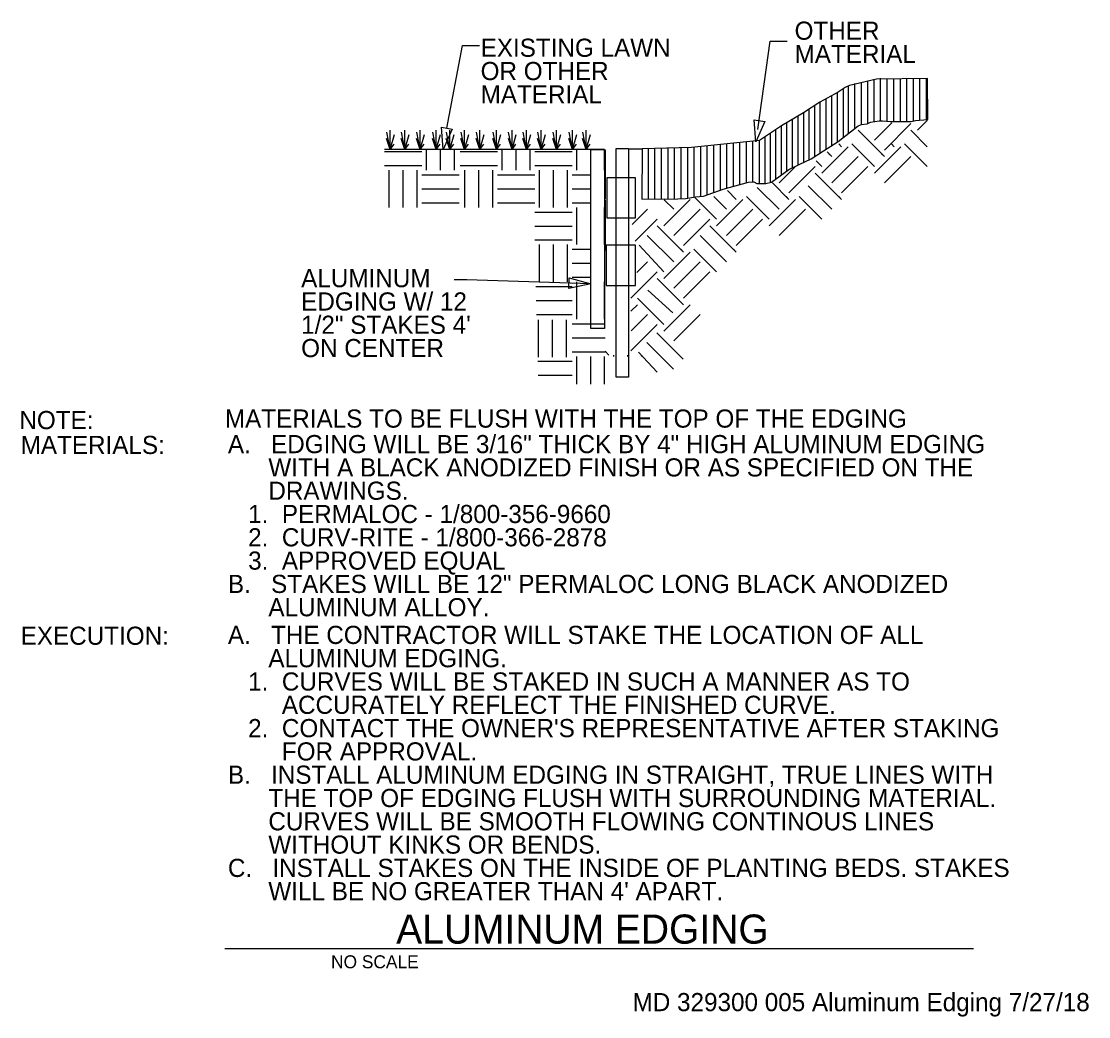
# Model space of a CAD drawing. Extents: x 10145.4 to 10186.6, y 9970.3 to 10008.7.
import ezdxf

# ---------------------------------------------------------------- set-up
doc = ezdxf.new("R2010")
doc.units = 0
for name, color, linetype in [('Default', 7, 'Continuous'), ('G-ANNO-CELL', 7, 'Continuous'), ('G-ANNO-TEXT', 7, 'Continuous'), ('G-DETL-GRID', 7, 'Continuous'), ('G-DETL-LINE', 7, 'Continuous'), ('G-DETL-OTLN', 7, 'Continuous'), ('G-DETL-PATT', 7, 'Continuous'), ('G-DETL-TEXT', 7, 'Continuous')]:
    doc.layers.add(name, color=color, linetype=linetype)

# ---------------------------------------------------------------- blocks, each defined once
blk = doc.blocks.new('TERARR')
at = {"layer": 'Default'}
blk.add_lwpolyline([(-0.667, 0.167), (0, 0), (-0.667, -0.167)], close=True, dxfattribs=at)

msp = doc.modelspace()

# ---------------------------------------------------------------- linework, layer by layer
at = {"layer": 'G-ANNO-TEXT'}
msp.add_line((10153.294, 9972.936), (10182.188, 9972.936), dxfattribs=at)
msp.add_line((10153.294, 9972.936), (10182.188, 9972.936), dxfattribs=at)
at = {"layer": 'G-DETL-LINE'}
for p, q in [((10159.674, 10003.773), (10159.532, 10004.193)), ((10159.674, 10003.773), (10159.544, 10004.437)), ((10159.674, 10003.773), (10159.674, 10004.513)), ((10159.674, 10003.773), (10159.84, 10004.346)), ((10160.236, 10003.773), (10160.094, 10004.193)), ((10160.236, 10003.773), (10160.106, 10004.437)), ((10160.236, 10003.773), (10160.236, 10004.513)), ((10160.236, 10003.773), (10160.402, 10004.346)), ((10160.827, 10003.773), (10160.685, 10004.193)), ((10160.827, 10003.773), (10160.697, 10004.437)), ((10160.827, 10003.773), (10160.827, 10004.513)), ((10160.827, 10003.773), (10160.993, 10004.346)), ((10161.447, 10003.773), (10161.305, 10004.193)), ((10161.447, 10003.773), (10161.317, 10004.437)), ((10161.447, 10003.773), (10161.447, 10004.513)), ((10161.447, 10003.773), (10161.613, 10004.346)), ((10161.979, 10003.773), (10161.838, 10004.193)), ((10161.979, 10003.773), (10161.838, 10004.193)), ((10161.979, 10003.773), (10161.85, 10004.437)), ((10161.979, 10003.773), (10161.85, 10004.437)), ((10161.979, 10003.773), (10161.979, 10004.513)), ((10161.979, 10003.773), (10161.979, 10004.513)), ((10161.979, 10003.773), (10162.145, 10004.346)), ((10161.979, 10003.773), (10162.145, 10004.346)), ((10162.541, 10003.773), (10162.399, 10004.193)), ((10162.541, 10003.773), (10162.412, 10004.437)), ((10162.541, 10003.773), (10162.541, 10004.513)), ((10162.541, 10003.773), (10162.707, 10004.346)), ((10163.132, 10003.773), (10162.99, 10004.193)), ((10163.132, 10003.773), (10163.003, 10004.437)), ((10163.132, 10003.773), (10163.132, 10004.513)), ((10163.132, 10003.773), (10163.298, 10004.346)), ((10163.782, 10003.773), (10163.64, 10004.193)), ((10163.782, 10003.773), (10163.652, 10004.437)), ((10163.782, 10003.773), (10163.782, 10004.513)), ((10163.782, 10003.773), (10163.948, 10004.346)), ((10164.375, 10003.773), (10164.234, 10004.193)), ((10164.375, 10003.773), (10164.246, 10004.437)), ((10164.375, 10003.773), (10164.375, 10004.513)), ((10164.375, 10003.773), (10164.541, 10004.346)), ((10164.937, 10003.773), (10164.795, 10004.193)), ((10164.937, 10003.773), (10164.808, 10004.437)), ((10164.937, 10003.773), (10164.937, 10004.513)), ((10164.937, 10003.773), (10165.103, 10004.346)), ((10165.499, 10003.773), (10165.357, 10004.193)), ((10165.499, 10003.773), (10165.369, 10004.437)), ((10165.499, 10003.773), (10165.499, 10004.513)), ((10165.499, 10003.773), (10165.665, 10004.346)), ((10166.09, 10003.773), (10165.948, 10004.193)), ((10166.09, 10003.773), (10165.96, 10004.437)), ((10166.09, 10003.773), (10166.09, 10004.513)), ((10166.09, 10003.773), (10166.256, 10004.346)), ((10166.71, 10003.773), (10166.569, 10004.193)), ((10166.71, 10003.773), (10166.581, 10004.437)), ((10166.71, 10003.773), (10166.71, 10004.513)), ((10166.71, 10003.773), (10166.876, 10004.346)), ((10167.243, 10003.773), (10167.101, 10004.193)), ((10167.243, 10003.773), (10167.113, 10004.437)), ((10167.243, 10003.773), (10167.243, 10004.513)), ((10167.243, 10003.773), (10167.409, 10004.346)), ((10159.674, 10003.773), (10159.828, 10003.975)), ((10160.236, 10003.773), (10160.389, 10003.975)), ((10160.827, 10003.773), (10160.98, 10003.975)), ((10161.447, 10003.773), (10161.601, 10003.975)), ((10161.979, 10003.773), (10162.133, 10003.975)), ((10161.979, 10003.773), (10162.133, 10003.975)), ((10162.541, 10003.773), (10162.695, 10003.975)), ((10163.132, 10003.773), (10163.286, 10003.975)), ((10163.782, 10003.773), (10163.936, 10003.975)), ((10164.375, 10003.773), (10164.529, 10003.975)), ((10164.937, 10003.773), (10165.091, 10003.975)), ((10165.499, 10003.773), (10165.653, 10003.975)), ((10166.09, 10003.773), (10166.244, 10003.975)), ((10166.71, 10003.773), (10166.864, 10003.975)), ((10167.243, 10003.773), (10167.397, 10003.975))]:
    msp.add_line(p, q, dxfattribs=at)
at = {"layer": 'G-DETL-OTLN'}
for p, q in [((10177.402, 10006.238), (10177.236, 10006.163)), ((10178.442, 10006.493), (10177.402, 10006.238)), ((10180.407, 10006.515), (10178.442, 10006.493)), ((10180.425, 10004.926), (10180.407, 10006.515)), ((10176.958, 10005.98), (10176.254, 10005.605)), ((10177.236, 10006.163), (10176.958, 10005.98)), ((10176.254, 10005.605), (10175.627, 10005.191)), ((10175.627, 10005.191), (10174.781, 10004.686)), ((10174.781, 10004.686), (10173.928, 10004.116)), ((10176.963, 10004.084), (10177.729, 10004.688)), ((10177.729, 10004.688), (10177.861, 10004.738)), ((10177.861, 10004.738), (10178.087, 10004.768)), ((10178.087, 10004.768), (10178.214, 10004.827)), ((10178.214, 10004.827), (10178.548, 10004.878)), ((10178.548, 10004.878), (10178.677, 10004.881)), ((10178.677, 10004.881), (10178.969, 10004.854)), ((10178.969, 10004.854), (10179.777, 10004.857)), ((10179.777, 10004.857), (10179.952, 10004.887)), ((10179.952, 10004.887), (10180.425, 10004.926)), ((10167.95, 10003.773), (10159.448, 10003.773)), ((10169.399, 10003.804), (10169.386, 10001.853)), ((10171.297, 10003.853), (10169.399, 10003.804)), ((10173.429, 10004.066), (10171.297, 10003.853)), ((10173.928, 10004.116), (10173.429, 10004.066)), ((10175.925, 10003.416), (10176.394, 10003.718)), ((10176.394, 10003.718), (10176.963, 10004.084)), ((10175.459, 10003.19), (10175.925, 10003.416)), ((10174.39, 10002.508), (10175.063, 10002.998)), ((10175.063, 10002.998), (10175.459, 10003.19)), ((10172.52, 10002.24), (10173.505, 10002.511)), ((10173.505, 10002.511), (10173.706, 10002.521)), ((10173.706, 10002.521), (10173.823, 10002.464)), ((10174.176, 10002.464), (10174.39, 10002.508)), ((10171.771, 10001.971), (10172.52, 10002.24)), ((10173.823, 10002.464), (10174.176, 10002.464)), ((10169.386, 10001.853), (10170.769, 10001.867)), ((10170.769, 10001.867), (10171.083, 10001.884)), ((10171.083, 10001.884), (10171.451, 10001.951)), ((10171.451, 10001.951), (10171.771, 10001.971))]:
    msp.add_line(p, q, dxfattribs=at)
for points in [[(10167.411, 10003.773), (10167.95, 10003.773), (10167.95, 9996.86), (10167.411, 9996.86)], [(10168.389, 10003.81), (10168.873, 10003.81), (10168.873, 9994.981), (10168.389, 9994.981)], [(10169.138, 10002.683), (10168.038, 10002.683), (10168.038, 10001.131), (10169.138, 10001.131)], [(10169.138, 10000.085), (10168.014, 10000.085), (10168.014, 9998.528), (10169.138, 9998.528)]]:
    msp.add_lwpolyline(points, close=True, dxfattribs=at)
for points in [[(10167.989, 10001.869), (10167.989, 10003.76)], [(10168.864, 10003.804), (10169.397, 10003.804)], [(10167.989, 9999.881), (10167.989, 10001.824)]]:
    msp.add_lwpolyline(points, dxfattribs=at)
at = {"layer": 'G-DETL-PATT'}
for p, q in [((10177.402, 10006.238), (10177.236, 10006.163)), ((10177.352, 10006.237), (10177.352, 10004.389)), ((10178.442, 10006.493), (10177.402, 10006.238)), ((10177.592, 10006.323), (10177.592, 10004.579)), ((10177.85, 10006.347), (10177.85, 10004.735)), ((10178.095, 10006.407), (10178.095, 10004.771)), ((10178.341, 10006.467), (10178.341, 10004.844)), ((10180.407, 10006.515), (10178.442, 10006.493)), ((10178.587, 10006.527), (10178.587, 10004.877)), ((10178.843, 10006.496), (10178.843, 10004.867)), ((10179.096, 10006.499), (10179.096, 10004.855)), ((10179.349, 10006.502), (10179.349, 10004.856)), ((10179.602, 10006.505), (10179.602, 10004.856)), ((10179.855, 10006.508), (10179.855, 10004.869)), ((10180.107, 10006.511), (10180.107, 10004.9)), ((10180.36, 10006.514), (10180.36, 10004.92)), ((10180.425, 10004.926), (10180.407, 10006.515)), ((10176.958, 10005.98), (10176.254, 10005.605)), ((10176.704, 10005.843), (10176.704, 10003.917)), ((10176.927, 10005.962), (10176.927, 10004.059)), ((10177.236, 10006.163), (10176.958, 10005.98)), ((10177.15, 10006.082), (10177.15, 10004.235)), ((10176.254, 10005.605), (10175.627, 10005.191)), ((10176.047, 10005.466), (10176.047, 10003.494)), ((10176.258, 10005.606), (10176.258, 10003.631)), ((10176.481, 10005.724), (10176.481, 10003.774)), ((10175.627, 10005.191), (10174.781, 10004.686)), ((10175.408, 10005.058), (10175.408, 10003.165)), ((10175.625, 10005.188), (10175.625, 10003.27)), ((10175.836, 10005.327), (10175.836, 10003.374)), ((10174.781, 10004.686), (10173.928, 10004.116)), ((10174.757, 10004.668), (10174.757, 10002.776)), ((10174.967, 10004.809), (10174.967, 10002.928)), ((10175.19, 10004.929), (10175.19, 10003.059)), ((10176.963, 10004.084), (10177.729, 10004.688)), ((10177.729, 10004.688), (10177.861, 10004.738)), ((10177.861, 10004.738), (10178.087, 10004.768)), ((10178.087, 10004.768), (10178.214, 10004.827)), ((10178.214, 10004.827), (10178.548, 10004.878)), ((10178.367, 10004.135), (10179.032, 10004.8)), ((10178.548, 10004.878), (10178.677, 10004.881)), ((10178.677, 10004.881), (10178.969, 10004.854)), ((10178.748, 10003.753), (10179.764, 10004.77)), ((10178.969, 10004.854), (10179.777, 10004.857)), ((10179.777, 10004.857), (10179.952, 10004.887)), ((10179.952, 10004.887), (10180.425, 10004.926)), ((10180.019, 10004.516), (10180.397, 10004.894)), ((10174.126, 10004.247), (10174.126, 10002.464)), ((10174.337, 10004.388), (10174.337, 10002.497)), ((10174.547, 10004.528), (10174.547, 10002.624)), ((10178.748, 10003.499), (10177.732, 10004.516)), ((10180.403, 10003.877), (10179.764, 10004.516)), ((10161.072, 10002.976), (10161.072, 10003.773)), ((10161.611, 10002.976), (10161.611, 10003.773)), ((10162.151, 10002.976), (10162.151, 10003.773)), ((10163.997, 10002.976), (10163.997, 10003.773)), ((10164.536, 10002.976), (10164.536, 10003.773)), ((10165.075, 10002.976), (10165.075, 10003.773)), ((10166.872, 10002.976), (10166.872, 10003.773)), ((10167.411, 10002.976), (10167.411, 10003.773)), ((10167.95, 10002.976), (10167.95, 10003.773)), ((10169.399, 10003.804), (10169.386, 10001.853)), ((10171.297, 10003.853), (10169.399, 10003.804)), ((10169.628, 10003.808), (10169.628, 10001.856)), ((10169.873, 10003.816), (10169.873, 10001.857)), ((10170.134, 10003.821), (10170.134, 10001.869)), ((10170.386, 10003.828), (10170.386, 10001.875)), ((10170.639, 10003.835), (10170.639, 10001.882)), ((10170.892, 10003.841), (10170.892, 10001.889)), ((10171.145, 10003.848), (10171.145, 10001.895)), ((10173.429, 10004.066), (10171.297, 10003.853)), ((10171.397, 10003.854), (10171.397, 10001.941)), ((10171.649, 10003.887), (10171.649, 10001.963)), ((10171.9, 10003.912), (10171.9, 10002.017)), ((10172.152, 10003.937), (10172.152, 10002.11)), ((10172.403, 10003.963), (10172.403, 10002.197)), ((10172.655, 10003.988), (10172.655, 10002.279)), ((10172.907, 10004.013), (10172.907, 10002.345)), ((10173.158, 10004.038), (10173.158, 10002.417)), ((10173.41, 10004.063), (10173.41, 10002.485)), ((10173.928, 10004.116), (10173.429, 10004.066)), ((10173.661, 10004.088), (10173.661, 10002.518)), ((10173.913, 10004.114), (10173.913, 10002.465)), ((10175.925, 10003.416), (10176.394, 10003.718)), ((10176.334, 10002.864), (10177.35, 10003.881)), ((10176.394, 10003.718), (10176.963, 10004.084)), ((10177.096, 10003.881), (10176.987, 10003.989)), ((10178.367, 10003.118), (10177.496, 10003.989)), ((10178.748, 10003.499), (10178.258, 10003.989)), ((10178.367, 10002.864), (10179.383, 10003.881)), ((10179.129, 10003.881), (10179.02, 10003.989)), ((10180.4, 10003.118), (10179.528, 10003.989)), ((10179.56, 10004.049), (10179.56, 10004.049)), ((10180.371, 10003.995), (10180.371, 10003.995)), ((10159.455, 10003.694), (10160.893, 10003.694)), ((10162.38, 10003.694), (10163.817, 10003.694)), ((10165.255, 10003.694), (10166.692, 10003.694)), ((10175.459, 10003.19), (10175.925, 10003.416)), ((10176.334, 10003.118), (10176.116, 10003.336)), ((10176.715, 10003.499), (10176.532, 10003.682)), ((10176.715, 10003.499), (10176.606, 10003.608)), ((10176.715, 10002.483), (10177.732, 10003.499)), ((10178.748, 10003.499), (10178.639, 10003.608)), ((10178.748, 10002.483), (10179.764, 10003.499)), ((10179.179, 10003.667), (10179.179, 10003.667)), ((10179.989, 10003.614), (10179.989, 10003.614)), ((10159.455, 10003.155), (10160.893, 10003.155)), ((10159.635, 10001.538), (10159.635, 10002.976)), ((10160.174, 10001.538), (10160.174, 10002.976)), ((10160.713, 10001.538), (10160.713, 10002.976)), ((10162.38, 10003.155), (10163.817, 10003.155)), ((10162.559, 10001.538), (10162.559, 10002.976)), ((10163.098, 10001.538), (10163.098, 10002.976)), ((10163.637, 10001.538), (10163.637, 10002.976)), ((10165.255, 10003.155), (10166.692, 10003.155)), ((10165.434, 10001.538), (10165.434, 10002.976)), ((10165.973, 10001.538), (10165.973, 10002.976)), ((10166.512, 10001.538), (10166.512, 10002.976)), ((10174.39, 10002.508), (10175.063, 10002.998)), ((10174.682, 10002.483), (10175.284, 10003.085)), ((10175.063, 10002.998), (10175.459, 10003.19)), ((10175.063, 10002.102), (10176.08, 10003.118)), ((10177.096, 10002.102), (10178.113, 10003.118)), ((10160.893, 10002.796), (10162.33, 10002.796)), ((10163.817, 10002.796), (10165.255, 10002.796)), ((10166.692, 10002.796), (10167.419, 10002.796)), ((10172.52, 10002.24), (10173.505, 10002.511)), ((10173.505, 10002.511), (10173.706, 10002.521)), ((10173.706, 10002.521), (10173.823, 10002.464)), ((10174.176, 10002.464), (10174.39, 10002.508)), ((10175.063, 10001.848), (10174.425, 10002.485)), ((10177.096, 10001.848), (10176.08, 10002.864)), ((10160.893, 10002.257), (10162.33, 10002.257)), ((10163.817, 10002.257), (10165.255, 10002.257)), ((10166.692, 10002.257), (10167.419, 10002.257)), ((10171.771, 10001.971), (10172.52, 10002.24)), ((10173.03, 10001.848), (10172.686, 10002.192)), ((10173.823, 10002.464), (10174.176, 10002.464)), ((10174.682, 10001.466), (10173.837, 10002.311)), ((10176.715, 10001.466), (10175.81, 10002.371)), ((10160.893, 10001.718), (10162.33, 10001.718)), ((10163.817, 10001.718), (10165.255, 10001.718)), ((10166.692, 10001.718), (10167.426, 10001.718)), ((10169.386, 10001.853), (10170.769, 10001.867)), ((10170.235, 10000.831), (10171.252, 10001.848)), ((10170.616, 10001.466), (10170.249, 10001.834)), ((10170.769, 10001.867), (10171.083, 10001.884)), ((10171.083, 10001.884), (10171.451, 10001.951)), ((10172.268, 10001.085), (10171.397, 10001.957)), ((10171.451, 10001.951), (10171.771, 10001.971)), ((10172.649, 10001.466), (10172.159, 10001.957)), ((10172.268, 10000.831), (10173.284, 10001.848)), ((10174.301, 10001.085), (10173.43, 10001.957)), ((10174.301, 10000.831), (10175.317, 10001.848)), ((10175.063, 10001.848), (10174.954, 10001.957)), ((10175.063, 10001.848), (10174.954, 10001.957)), ((10175.283, 10002.001), (10175.283, 10002.001)), ((10175.283, 10002.001), (10175.283, 10002.001)), ((10176.334, 10001.085), (10175.463, 10001.957)), ((10177.096, 10001.848), (10176.987, 10001.957)), ((10177.096, 10001.848), (10176.987, 10001.957)), ((10165.255, 10001.358), (10166.692, 10001.358)), ((10166.872, 10000.101), (10166.872, 10001.538)), ((10167.411, 10000.101), (10167.411, 10001.538)), ((10167.95, 10000.101), (10167.95, 10001.538)), ((10168.867, 10001.631), (10168.867, 10001.631)), ((10169.008, 10000.874), (10169.6, 10001.466)), ((10170.616, 10000.45), (10171.633, 10001.466)), ((10172.649, 10000.45), (10173.666, 10001.466)), ((10174.682, 10000.45), (10175.699, 10001.466)), ((10168.82, 10001.112), (10168.82, 10001.112)), ((10169.129, 10000.233), (10169.981, 10001.085)), ((10170.997, 9999.815), (10169.981, 10000.831)), ((10170.997, 10000.069), (10172.014, 10001.085)), ((10173.03, 9999.815), (10172.014, 10000.831)), ((10173.03, 10000.069), (10174.047, 10001.085)), ((10165.255, 10000.819), (10166.692, 10000.819)), ((10170.616, 9999.433), (10169.595, 10000.455)), ((10172.649, 9999.433), (10171.633, 10000.45)), ((10165.255, 10000.28), (10166.692, 10000.28)), ((10165.434, 9998.663), (10165.434, 10000.101)), ((10165.973, 9998.663), (10165.973, 10000.101)), ((10166.512, 9998.663), (10166.512, 10000.101)), ((10169.124, 10000.101), (10169.124, 10000.101)), ((10169.277, 10000.084), (10169.277, 10000.084)), ((10170.235, 9999.052), (10169.277, 10000.084)), ((10166.692, 9999.921), (10167.41, 9999.921)), ((10170.235, 9998.798), (10171.252, 9999.815)), ((10170.997, 9999.815), (10170.888, 9999.924)), ((10172.268, 9999.052), (10171.397, 9999.924)), ((10172.649, 9999.433), (10172.159, 9999.924)), ((10173.03, 9999.815), (10172.921, 9999.924)), ((10166.692, 9999.382), (10167.41, 9999.382)), ((10169.193, 9999.027), (10169.6, 9999.433)), ((10170.616, 9998.417), (10171.633, 9999.433)), ((10166.692, 9998.843), (10167.414, 9998.843)), ((10168.964, 9998.036), (10169.981, 9999.052)), ((10170.997, 9997.782), (10169.981, 9998.798)), ((10170.997, 9998.036), (10172.014, 9999.052)), ((10165.292, 9998.483), (10166.692, 9998.483)), ((10166.872, 9997.226), (10166.872, 9998.663)), ((10167.411, 9997.226), (10167.411, 9998.663)), ((10167.95, 9997.226), (10167.95, 9998.663)), ((10165.306, 9997.944), (10166.692, 9997.944)), ((10170.235, 9997.019), (10169.219, 9998.036)), ((10169.616, 9998.342), (10170.577, 9997.47)), ((10168.964, 9997.528), (10169.219, 9997.782)), ((10170.235, 9996.765), (10171.252, 9997.782)), ((10165.32, 9997.405), (10166.692, 9997.405)), ((10165.394, 9995.764), (10165.394, 9997.202)), ((10165.933, 9995.764), (10165.933, 9997.202)), ((10166.472, 9995.764), (10166.472, 9997.202)), ((10168.975, 9996.776), (10169.6, 9997.401)), ((10170.616, 9996.384), (10171.633, 9997.401)), ((10166.692, 9997.046), (10167.964, 9997.046)), ((10168.964, 9996.003), (10169.981, 9997.019)), ((10166.692, 9996.507), (10167.964, 9996.507)), ((10170.601, 9995.301), (10169.58, 9996.322)), ((10170.982, 9995.682), (10169.966, 9996.699)), ((10166.692, 9995.968), (10167.964, 9995.968)), ((10168.11, 9995.841), (10167.964, 9995.987)), ((10169.98, 9995.178), (10169.262, 9995.951)), ((10165.37, 9995.608), (10166.692, 9995.608)), ((10166.872, 9994.71), (10166.872, 9995.788)), ((10167.411, 9994.71), (10167.411, 9995.788)), ((10167.95, 9994.71), (10167.95, 9995.788)), ((10168.309, 9995.788), (10168.309, 9995.841)), ((10168.848, 9995.788), (10168.848, 9995.841)), ((10169.387, 9995.788), (10169.387, 9995.841)), ((10165.386, 9995.069), (10166.692, 9995.069))]:
    msp.add_line(p, q, dxfattribs=at)
for points in [[(10173.864, 10004.538), (10174.336, 10007.953), (10174.992, 10007.953)], [(10161.857, 10004.596), (10162.466, 10007.78), (10163.122, 10007.78)], [(10167.411, 9998.588), (10162.633, 9998.749), (10162.14, 9998.749)]]:
    msp.add_lwpolyline(points, dxfattribs=at)

# ---------------------------------------------------------------- block references
for p, xscale, yscale, rotation in [((10161.722, 10003.774), 1.2500000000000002, 1.25, -99.35282054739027), ((10173.788, 10004.065), 1.2500000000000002, 1.25, -99.35282054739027), ((10167.411, 9998.588), 1.25, 1.2500000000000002, -1.9239204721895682)]:
    msp.add_blockref('TERARR', p, dxfattribs=dict(at, xscale=xscale, yscale=yscale, rotation=rotation))

# ---------------------------------------------------------------- texts
at = {"layer": 'G-ANNO-CELL'}
for s, height, p in [('NO SCALE', 0.5, (10157.392, 9972.175)), ('MD 329300 005 Aluminum Edging 7/27/18', 0.7, (10169.029, 9970.519))]:
    msp.add_text(s, height=height, dxfattribs=at).set_placement(p)
at = {"layer": 'G-DETL-GRID'}
msp.add_text('ALUMINUM EDGING', height=1.125, dxfattribs=at).set_placement((10159.905, 9973.124))
at = {"layer": 'G-DETL-TEXT'}
for s, p in [('OTHER ', (10175.28, 10008.008)), ('EXISTING LAWN ', (10163.164, 10007.35)), ('MATERIAL', (10175.28, 10007.109)), ('OR OTHER ', (10163.164, 10006.451)), ('MATERIAL', (10163.164, 10005.551)), ('ALUMINUM ', (10156.238, 9998.457)), ('EDGING W/ 12 ', (10156.238, 9997.558)), ('1/2" STAKES 4\' ', (10156.238, 9996.659)), ('ON CENTER', (10156.238, 9995.76)), ('NOTE:', (10145.363, 9992.982)), ('MATERIALS TO BE FLUSH WITH THE TOP OF THE EDGING', (10153.295, 9993.039)), ('MATERIALS:', (10145.413, 9992.022)), ('A.   EDGING WILL BE 3/16" THICK BY 4" HIGH ALUMINUM EDGING ', (10153.412, 9992.053)), ('      WITH A BLACK ANODIZED FINISH OR AS SPECIFIED ON THE ', (10153.412, 9991.154)), ('      DRAWINGS.', (10153.412, 9990.255)), ('   1.  PERMALOC - 1/800-356-9660', (10153.412, 9989.356)), ('   2.  CURV-RITE - 1/800-366-2878', (10153.412, 9988.457)), ('   3.  APPROVED EQUAL', (10153.412, 9987.558)), ('B.   STAKES WILL BE 12" PERMALOC LONG BLACK ANODIZED ', (10153.412, 9986.658)), ('      ALUMINUM ALLOY.', (10153.412, 9985.759)), ('EXECUTION:', (10145.413, 9984.658)), ('A.   THE CONTRACTOR WILL STAKE THE LOCATION OF ALL ', (10153.412, 9984.69)), ('      ALUMINUM EDGING.', (10153.412, 9983.791)), ('   1.  CURVES WILL BE STAKED IN SUCH A MANNER AS TO ', (10153.412, 9982.892)), ('        ACCURATELY REFLECT THE FINISHED CURVE.', (10153.412, 9981.993)), ("   2.  CONTACT THE OWNER'S REPRESENTATIVE AFTER STAKING ", (10153.412, 9981.093)), ('        FOR APPROVAL.', (10153.412, 9980.194)), ('B.   INSTALL ALUMINUM EDGING IN STRAIGHT, TRUE LINES WITH ', (10153.412, 9979.295)), ('      THE TOP OF EDGING FLUSH WITH SURROUNDING MATERIAL. ', (10153.412, 9978.396)), ('      CURVES WILL BE SMOOTH FLOWING CONTINOUS LINES ', (10153.412, 9977.497)), ('      WITHOUT KINKS OR BENDS. ', (10153.412, 9976.598)), ('C.   INSTALL STAKES ON THE INSIDE OF PLANTING BEDS. STAKES ', (10153.412, 9975.699)), ("      WILL BE NO GREATER THAN 4' APART.", (10153.412, 9974.8))]:
    msp.add_text(s, height=0.7, dxfattribs=at).set_placement(p)

doc.saveas('drawing.dxf')
